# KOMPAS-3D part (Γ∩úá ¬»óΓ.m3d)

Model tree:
1. Эскиз:1
2. Операция выдавливания:1
     Расстояние 1 = 26.9; Расстояние 2 = 1
3. Эскиз:2
4. Операция выдавливания:2
     Расстояние 1 = 0.7; Расстояние 2 = 0.7
5. Эскиз:3
6. Вырезать элемент выдавливания:1
     Расстояние 2 = 2; Расстояние 1 = 2
7. Скругление:1
     Радиус = 0.1
8. Скругление:2
     Радиус = 0.1
9. Эскиз:4
10. Вырезать элемент выдавливания:2
     Расстояние 2 = 2; Расстояние 1 = 2
11. Массив по концентрической сетке:2  (with: Вырезать элемент выдавливания:2)  (labels: Экземпляр ( 1, 1 ); Экземпляр ( 1, 2 ); Экземпляр ( 1, 3 ); Экземпляр ( 1, 4 ))
     N 2 = 11; Шаг 2 = 360; Номер 2 = 1

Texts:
  Сплав АЛ8  ГОСТ 1583-93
